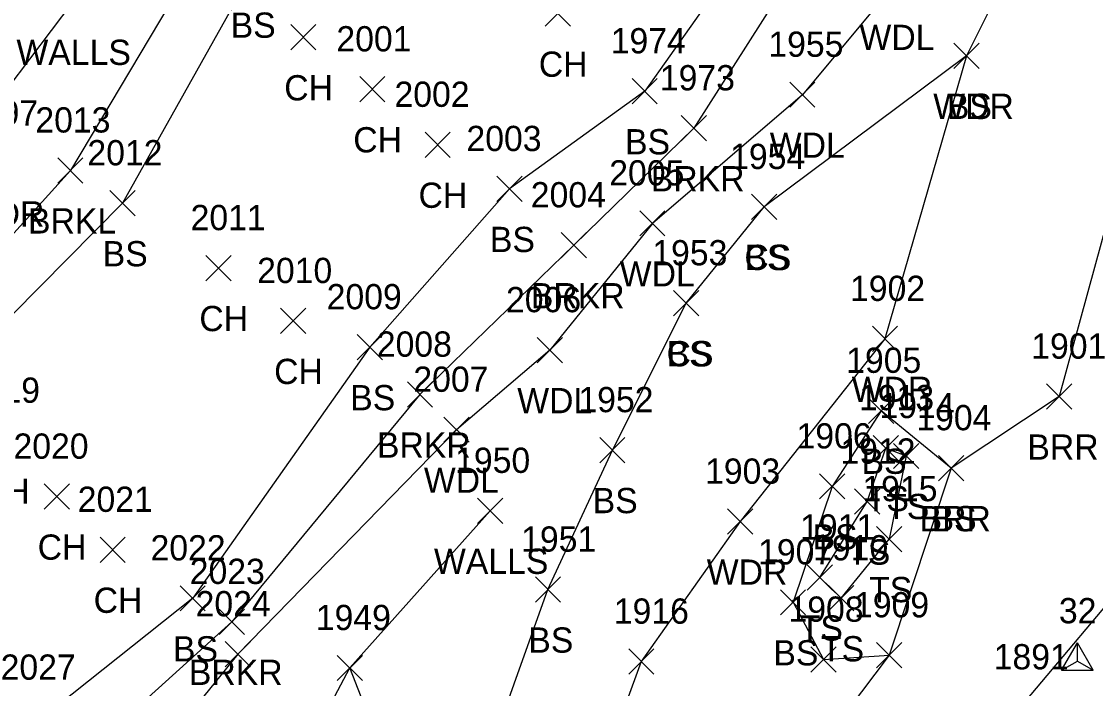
# Model space of a CAD drawing. Extents: x 1499292 to 1501024, y 534584 to 538043.
# Drawn here: x 1499887.8 to 1499972.9, y 537739.6 to 537792.4 of the extents above; entities that cross this region are included whole.
import ezdxf

# ---------------------------------------------------------------- set-up
doc = ezdxf.new("R2010")
doc.units = 0
for name, color, linetype in [('C_I', 7, 'Continuous'), ('CPSM', 7, 'Continuous'), ('L_A', 7, 'Continuous'), ('L_I', 7, 'Continuous'), ('L_TIC', 7, 'Continuous'), ('LABL', 7, 'Continuous'), ('LAWA', 7, 'Continuous'), ('LAWE', 7, 'Continuous'), ('LELB', 7, 'Continuous'), ('LWS', 7, 'Continuous')]:
    doc.layers.add(name, color=color, linetype=linetype)

msp = doc.modelspace()

# ---------------------------------------------------------------- linework, layer by layer
at = {"layer": 'CPSM'}
for p, q in [((1499970.243, 537741.016), (1499971.493, 537743.181)), ((1499972.743, 537741.016), (1499971.493, 537743.181)), ((1499971.494, 537741.737), (1499971.493, 537743.181)), ((1499970.243, 537741.016), (1499971.494, 537741.737)), ((1499971.494, 537741.737), (1499971.494, 537741.737)), ((1499971.494, 537741.737), (1499972.743, 537741.016)), ((1499970.243, 537741.016), (1499972.743, 537741.016))]:
    msp.add_line(p, q, dxfattribs=at)
at = {"layer": 'L_TIC'}
for points in [[(1499929.329, 537792.025), (1499931.329, 537794.025)], [(1499931.329, 537792.025), (1499929.329, 537794.025)], [(1499909.156, 537790.155), (1499911.156, 537792.155)], [(1499911.156, 537790.155), (1499909.156, 537792.155)], [(1499961.707, 537788.685), (1499963.707, 537790.685)], [(1499963.707, 537788.685), (1499961.707, 537790.685)], [(1499961.707, 537788.685), (1499963.707, 537790.685)], [(1499963.707, 537788.685), (1499961.707, 537790.685)], [(1499914.627, 537786.036), (1499916.627, 537788.036)], [(1499916.627, 537786.036), (1499914.627, 537788.036)], [(1499936.207, 537785.88), (1499938.207, 537787.88)], [(1499938.207, 537785.88), (1499936.207, 537787.88)], [(1499948.698, 537785.608), (1499950.698, 537787.608)], [(1499950.698, 537785.608), (1499948.698, 537787.608)], [(1499940.102, 537782.95), (1499942.102, 537784.95)], [(1499942.102, 537782.95), (1499940.102, 537784.95)], [(1499919.799, 537781.645), (1499921.799, 537783.645)], [(1499921.799, 537781.645), (1499919.799, 537783.645)], [(1499890.697, 537779.61), (1499892.697, 537781.61)], [(1499892.697, 537779.61), (1499890.697, 537781.61)], [(1499925.5, 537778.141), (1499927.5, 537780.141)], [(1499927.5, 537778.141), (1499925.5, 537780.141)], [(1499894.821, 537777.011), (1499896.821, 537779.011)], [(1499896.821, 537777.011), (1499894.821, 537779.011)], [(1499945.667, 537776.717), (1499947.667, 537778.717)], [(1499947.667, 537776.717), (1499945.667, 537778.717)], [(1499945.667, 537776.717), (1499947.667, 537778.717)], [(1499947.667, 537776.717), (1499945.667, 537778.717)], [(1499936.814, 537775.416), (1499938.814, 537777.416)], [(1499938.814, 537775.416), (1499936.814, 537777.416)], [(1499930.596, 537773.682), (1499932.596, 537775.682)], [(1499932.596, 537773.682), (1499930.596, 537775.682)], [(1499902.431, 537771.876), (1499904.431, 537773.876)], [(1499904.431, 537771.876), (1499902.431, 537773.876)], [(1499939.501, 537769.089), (1499941.501, 537771.089)], [(1499941.501, 537769.089), (1499939.501, 537771.089)], [(1499939.501, 537769.089), (1499941.501, 537771.089)], [(1499941.501, 537769.089), (1499939.501, 537771.089)], [(1499908.357, 537767.687), (1499910.357, 537769.687)], [(1499910.357, 537767.687), (1499908.357, 537769.687)], [(1499914.434, 537765.609), (1499916.434, 537767.609)], [(1499916.434, 537765.609), (1499914.434, 537767.609)], [(1499955.245, 537766.268), (1499957.245, 537768.268)], [(1499957.245, 537766.268), (1499955.245, 537768.268)], [(1499928.69, 537765.375), (1499930.69, 537767.375)], [(1499930.69, 537765.375), (1499928.69, 537767.375)], [(1499918.4, 537761.854), (1499920.4, 537763.854)], [(1499920.4, 537761.854), (1499918.4, 537763.854)], [(1499969.041, 537761.697), (1499971.041, 537763.697)], [(1499971.041, 537761.697), (1499969.041, 537763.697)], [(1499954.945, 537760.574), (1499956.945, 537762.574)], [(1499956.945, 537760.574), (1499954.945, 537762.574)], [(1499921.293, 537759.072), (1499923.293, 537761.072)], [(1499923.293, 537759.072), (1499921.293, 537761.072)], [(1499933.646, 537757.458), (1499935.646, 537759.458)], [(1499935.646, 537757.458), (1499933.646, 537759.458)], [(1499955.314, 537757.616), (1499957.314, 537759.616)], [(1499957.314, 537757.616), (1499955.314, 537759.616)], [(1499956.933, 537756.989), (1499958.933, 537758.989)], [(1499958.933, 537756.989), (1499956.933, 537758.989)], [(1499960.498, 537756.027), (1499962.498, 537758.027)], [(1499962.498, 537756.027), (1499960.498, 537758.027)], [(1499960.498, 537756.027), (1499962.498, 537758.027)], [(1499962.498, 537756.027), (1499960.498, 537758.027)], [(1499951.065, 537754.584), (1499953.065, 537756.584)], [(1499953.065, 537754.584), (1499951.065, 537756.584)], [(1499889.619, 537753.772), (1499891.619, 537755.772)], [(1499891.619, 537753.772), (1499889.619, 537755.772)], [(1499953.843, 537753.382), (1499955.843, 537755.382)], [(1499955.843, 537753.382), (1499953.843, 537755.382)], [(1499923.965, 537752.649), (1499925.965, 537754.649)], [(1499925.965, 537752.649), (1499923.965, 537754.649)], [(1499943.762, 537751.791), (1499945.762, 537753.791)], [(1499945.762, 537751.791), (1499943.762, 537753.791)], [(1499955.582, 537750.407), (1499957.582, 537752.407)], [(1499957.582, 537750.407), (1499955.582, 537752.407)], [(1499955.582, 537750.407), (1499957.582, 537752.407)], [(1499957.582, 537750.407), (1499955.582, 537752.407)], [(1499894.053, 537749.563), (1499896.053, 537751.563)], [(1499896.053, 537749.563), (1499894.053, 537751.563)], [(1499950.084, 537747.364), (1499952.084, 537749.364)], [(1499952.084, 537747.364), (1499950.084, 537749.364)], [(1499928.543, 537746.41), (1499930.543, 537748.41)], [(1499930.543, 537746.41), (1499928.543, 537748.41)], [(1499900.39, 537745.714), (1499902.39, 537747.714)], [(1499902.39, 537745.714), (1499900.39, 537747.714)], [(1499947.961, 537745.4), (1499949.961, 537747.4)], [(1499949.961, 537745.4), (1499947.961, 537747.4)], [(1499951.765, 537745.719), (1499953.765, 537747.719)], [(1499953.765, 537745.719), (1499951.765, 537747.719)], [(1499951.765, 537745.719), (1499953.765, 537747.719)], [(1499953.765, 537745.719), (1499951.765, 537747.719)], [(1499903.496, 537743.851), (1499905.496, 537745.851)], [(1499905.496, 537743.851), (1499903.496, 537745.851)], [(1499903.962, 537741.29), (1499905.962, 537743.29)], [(1499905.962, 537741.29), (1499903.962, 537743.29)], [(1499950.372, 537740.86), (1499952.372, 537742.86)], [(1499952.372, 537740.86), (1499950.372, 537742.86)], [(1499955.574, 537741.207), (1499957.574, 537743.207)], [(1499957.574, 537741.207), (1499955.574, 537743.207)], [(1499955.574, 537741.207), (1499957.574, 537743.207)], [(1499957.574, 537741.207), (1499955.574, 537743.207)], [(1499912.848, 537740.196), (1499914.848, 537742.196)], [(1499914.848, 537740.196), (1499912.848, 537742.196)], [(1499912.848, 537740.196), (1499914.848, 537742.196)], [(1499914.848, 537740.196), (1499912.848, 537742.196)], [(1499935.939, 537740.705), (1499937.939, 537742.705)], [(1499937.939, 537740.705), (1499935.939, 537742.705)]]:
    msp.add_lwpolyline(points, dxfattribs=at)
at = {"layer": 'LABL'}
msp.add_lwpolyline([(1499985.467, 537801.862), (1499975.641, 537783.145), (1499970.041, 537762.697), (1499961.498, 537757.027), (1499956.574, 537742.207), (1499948.778, 537731.888), (1499940.204, 537717.909), (1499933.775, 537706.198), (1499925.612, 537690.188), (1499917.898, 537679.732), (1499908.462, 537671.894), (1499888.043, 537683.7), (1499880.149, 537690.561), (1499889.261, 537696.2)], dxfattribs=at)
at = {"layer": 'LAWA'}
for points in [[(1499965.845, 537814.607), (1499956.806, 537795.15), (1499949.698, 537786.608), (1499937.814, 537776.416), (1499929.69, 537766.375), (1499922.293, 537760.072), (1499904.962, 537742.29), (1499895.527, 537730.646), (1499881.146, 537718.435), (1499882.199, 537711.084), (1499876.181, 537705.711)], [(1499972.434, 537809.149), (1499962.707, 537789.685), (1499956.245, 537767.268), (1499944.762, 537752.791), (1499936.939, 537741.705), (1499930.814, 537724.983), (1499924.568, 537711.676), (1499920.036, 537699.678), (1499913.288, 537691.152), (1499908.677, 537691.352), (1499901.029, 537688.053), (1499897.226, 537689.74), (1499889.261, 537696.2), (1499876.181, 537705.711)]]:
    msp.add_lwpolyline(points, dxfattribs=at)
at = {"layer": 'LAWE'}
for points in [[(1499929.735, 537843.158), (1499921.146, 537828.37), (1499911.208, 537810.95), (1499902.71, 537799.071), (1499891.697, 537780.61), (1499878.475, 537765.999), (1499867.221, 537750.797), (1499855.373, 537733.552), (1499847.561, 537720.487), (1499833.234, 537714.677)], [(1499961.233, 537817.956), (1499952.785, 537802.28), (1499941.102, 537783.95), (1499931.596, 537774.682), (1499919.4, 537762.854), (1499904.496, 537744.851), (1499892.595, 537734.118), (1499878.532, 537718.766), (1499876.489, 537709.735), (1499874.077, 537712.657)]]:
    msp.add_lwpolyline(points, dxfattribs=at)
at = {"layer": 'LELB'}
for points in [[(1499931.33, 537841.299), (1499922.805, 537827.368), (1499912.716, 537807.848), (1499905.961, 537796.116), (1499895.821, 537778.011), (1499880.547, 537762.563), (1499870.857, 537749.776), (1499857.652, 537732.091), (1499849.894, 537720.064), (1499839.898, 537710.152), (1499830.869, 537699.252), (1499819.753, 537691.274), (1499813.247, 537682.443), (1499807.235, 537678.729), (1499801.402, 537680.954), (1499789.916, 537664.219), (1499779.135, 537655.089), (1499771.857, 537652.255), (1499758.583, 537645.464), (1499745.452, 537639.294), (1499734.398, 537633.246), (1499715.956, 537632.699), (1499700.464, 537632.224)], [(1499958.724, 537820.121), (1499949.099, 537803.701), (1499937.207, 537786.88), (1499926.5, 537779.141), (1499915.434, 537766.609), (1499901.39, 537746.714), (1499889.513, 537737.266), (1499877.766, 537721.1), (1499874.077, 537712.657), (1499871.122, 537712.1), (1499865.758, 537707.441), (1499861.535, 537702.351), (1499859.643, 537699.06)], [(1499962.707, 537789.685), (1499946.667, 537777.717)], [(1499940.501, 537770.089), (1499946.667, 537777.717)], [(1499897.226, 537689.74), (1499911.123, 537704.945), (1499918.862, 537717.524), (1499929.543, 537747.41), (1499934.646, 537758.458), (1499940.501, 537770.089)], [(1499961.498, 537757.027), (1499955.945, 537761.574), (1499952.065, 537755.584), (1499948.961, 537746.4), (1499951.372, 537741.86), (1499956.574, 537742.207)], [(1499949.249, 537680.121), (1499946.626, 537693.553), (1499957.831, 537706.678), (1499969.571, 537712.62), (1499957.119, 537727.603), (1499966.986, 537738.086), (1499985.845, 537760.478)], [(1499952.765, 537746.719), (1499951.084, 537748.364), (1499954.843, 537754.382), (1499956.314, 537758.616), (1499957.933, 537757.989), (1499956.582, 537751.407)], [(1499952.765, 537746.719), (1499956.582, 537751.407)], [(1499918.862, 537717.524), (1499918.27, 537729.854), (1499913.848, 537741.196)]]:
    msp.add_lwpolyline(points, dxfattribs=at)
at = {"layer": 'LWS'}
for points in [[(1499897.801, 537803.789), (1499891.884, 537793.964), (1499883.283, 537782.612), (1499874.394, 537769.047), (1499862.601, 537755.249), (1499849.481, 537739.229), (1499844.995, 537730.524)], [(1499908.876, 537731.828), (1499913.848, 537741.196), (1499924.965, 537753.649)]]:
    msp.add_lwpolyline(points, dxfattribs=at)

# ---------------------------------------------------------------- texts
at = {"layer": 'C_I'}
msp.add_text('32', height=2, dxfattribs=at).set_placement((1499970.029, 537744.737))
at = {"layer": 'L_A'}
for s, p in [('BS', (1499904.402, 537791.116)), ('WDL', (1499954.224, 537790.15)), ('WALLS', (1499887.427, 537788.964)), ('CH', (1499928.817, 537788.025)), ('CH', (1499908.645, 537786.155)), ('WDR', (1499960.07, 537784.685)), ('BS', (1499961.148, 537784.685)), ('CH', (1499914.115, 537782.036)), ('BS', (1499935.648, 537781.88)), ('WDL', (1499947.116, 537781.608)), ('BRKR', (1499937.692, 537778.95)), ('CH', (1499919.287, 537777.645)), ('WDR', (1499883.253, 537776.165)), ('BRKL', (1499888.343, 537775.61)), ('BS', (1499924.941, 537774.141)), ('BS', (1499894.261, 537773.011)), ('CS', (1499945.108, 537772.717)), ('BS', (1499945.108, 537772.717)), ('WDL', (1499935.231, 537771.416)), ('BRKR', (1499928.187, 537769.682)), ('CH', (1499901.919, 537767.876)), ('CS', (1499938.942, 537765.089)), ('BS', (1499938.942, 537765.089)), ('CH', (1499907.845, 537763.687)), ('WDR', (1499953.607, 537762.268)), ('BS', (1499913.874, 537761.609)), ('WDL', (1499927.107, 537761.375)), ('BRKR', (1499915.99, 537757.854)), ('BRR', (1499967.529, 537757.697)), ('BS', (1499954.386, 537756.574)), ('WDL', (1499919.71, 537755.072)), ('CH', (1499884.612, 537754.203)), ('TS', (1499954.723, 537753.616)), ('BS', (1499933.087, 537753.458)), ('TS', (1499956.343, 537752.989)), ('BRR', (1499958.987, 537752.027)), ('BS', (1499959.939, 537752.027)), ('BS', (1499950.506, 537750.584)), ('CH', (1499889.107, 537749.772)), ('TS', (1499953.252, 537749.382)), ('WALLS', (1499920.508, 537748.649)), ('WDR', (1499942.124, 537747.791)), ('TS', (1499954.991, 537746.407)), ('TS', (1499954.991, 537746.407)), ('CH', (1499893.542, 537745.563)), ('TS', (1499949.493, 537743.364)), ('BS', (1499899.83, 537741.714)), ('BS', (1499927.984, 537742.41)), ('TS', (1499951.175, 537741.719)), ('TS', (1499951.175, 537741.719)), ('BS', (1499947.402, 537741.4)), ('BRKR', (1499901.087, 537739.851))]:
    msp.add_text(s, height=2, dxfattribs=at).set_placement(p)
at = {"layer": 'L_I'}
for s, p in [('2001', (1499912.777, 537790.036)), ('1974', (1499934.514, 537789.88)), ('1955', (1499947.005, 537789.608)), ('1973', (1499938.409, 537786.95)), ('2002', (1499917.381, 537785.645)), ('1997', (1499883.198, 537784.165)), ('2013', (1499888.926, 537783.61)), ('2003', (1499923.082, 537782.141)), ('2012', (1499893.049, 537781.011)), ('1954', (1499943.974, 537780.717)), ('1954', (1499943.974, 537780.717)), ('2005', (1499934.397, 537779.416)), ('2004', (1499928.179, 537777.682)), ('2011', (1499901.226, 537775.876)), ('1953', (1499937.808, 537773.089)), ('1953', (1499937.808, 537773.089)), ('2010', (1499906.499, 537771.687)), ('1902', (1499953.474, 537770.268)), ('2009', (1499912.008, 537769.609)), ('2006', (1499926.217, 537769.375)), ('2008', (1499915.982, 537765.854)), ('1901', (1499967.836, 537765.697)), ('1905', (1499953.173, 537764.574)), ('2007', (1499918.876, 537763.072)), ('2019', (1499883.345, 537762.203)), ('1952', (1499931.953, 537761.458)), ('1913', (1499954.188, 537761.616)), ('1914', (1499955.807, 537760.989)), ('1904', (1499958.727, 537760.027)), ('1904', (1499958.727, 537760.027)), ('1906', (1499949.238, 537758.584)), ('2020', (1499887.193, 537757.772)), ('1912', (1499952.717, 537757.382)), ('1950', (1499922.185, 537756.649)), ('1903', (1499941.99, 537755.791)), ('1915', (1499954.456, 537754.407)), ('1915', (1499954.456, 537754.407)), ('2021', (1499892.282, 537753.563)), ('1911', (1499949.525, 537751.364)), ('1951', (1499927.417, 537750.41)), ('2022', (1499898.051, 537749.714)), ('1907', (1499946.19, 537749.4)), ('1910', (1499950.553, 537749.719)), ('1910', (1499950.553, 537749.719)), ('2023', (1499901.157, 537747.851)), ('2024', (1499901.624, 537745.29)), ('1909', (1499953.794, 537745.207)), ('1909', (1499953.794, 537745.207)), ('1949', (1499911.147, 537744.196)), ('1949', (1499911.147, 537744.196)), ('1916', (1499934.758, 537744.705)), ('1908', (1499948.601, 537744.86)), ('1891', (1499964.86, 537741.086)), ('2027', (1499886.174, 537740.266))]:
    msp.add_text(s, height=2, dxfattribs=at).set_placement(p)

doc.saveas('drawing.dxf')
